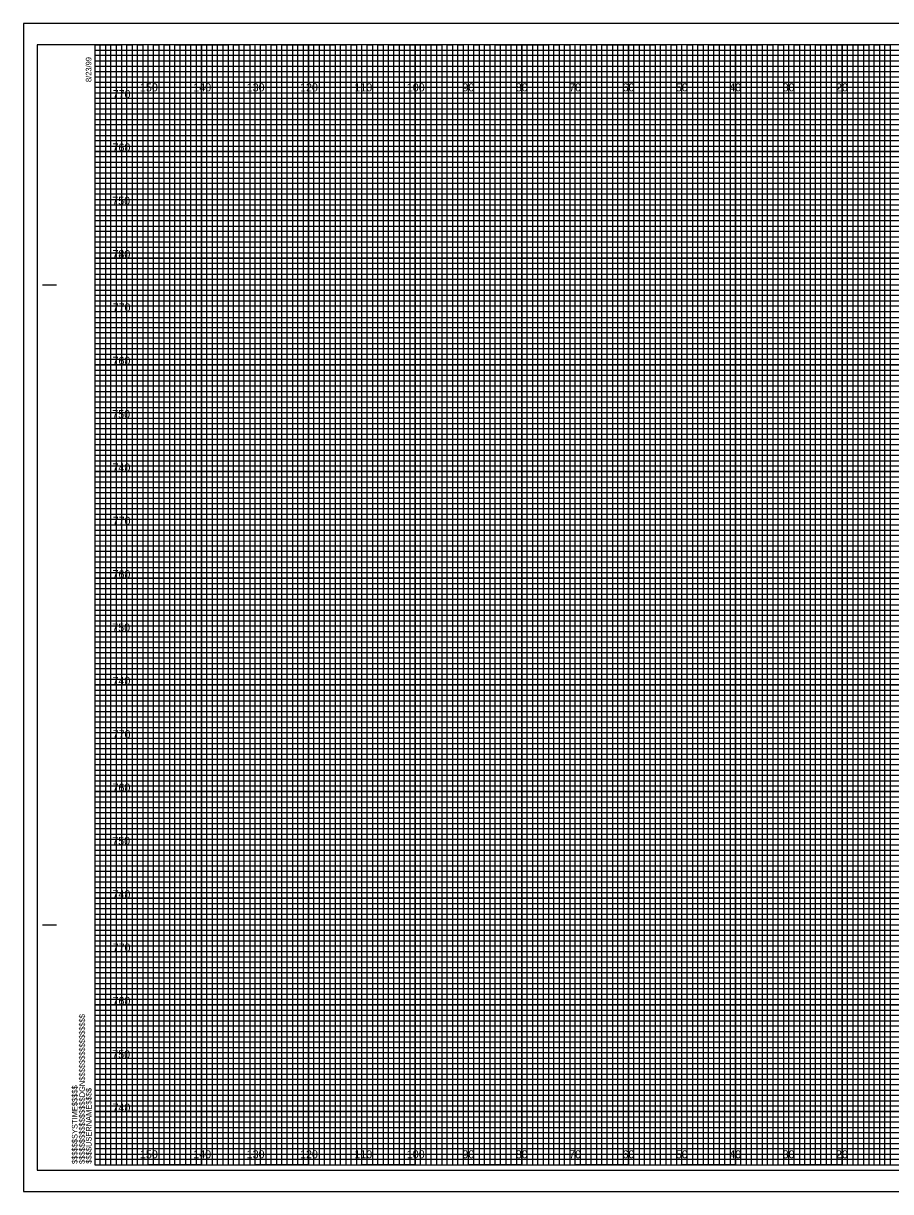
# Model space of a CAD drawing. Extents: x -13 to 323, y 435 to 654.
# Drawn here: x -13.4 to 149.1, y 435 to 654 of the extents above; entities that cross this region are included whole.
import ezdxf

# ---------------------------------------------------------------- set-up
doc = ezdxf.new("R2010")
doc.units = 0
for name, color, linetype in [('Exist Cross Section Cell', 7, 'Continuous'), ('Exist XS Ground Line', 7, 'Continuous'), ('Prop XS Ditch Slope Text', 7, 'Continuous'), ('Prop XS Dump Level', 7, 'Continuous'), ('Prop XS Finish Grade', 7, 'Continuous'), ('Prop XS Finish Grade Earthwork', 7, 'Continuous'), ('Prop XS Pvmt Edge Slope', 7, 'Continuous'), ('Prop XS SE Text', 7, 'Continuous'), ('Prop XS Side Slope Text', 7, 'Continuous'), ('Prop XS SS Elevation Text', 7, 'Continuous'), ('Prop XS Subgrade Earthwork', 7, 'Continuous')]:
    doc.layers.add(name, color=color, linetype=linetype)

msp = doc.modelspace()

# ---------------------------------------------------------------- linework, layer by layer
at = {"layer": 'Exist XS Ground Line'}
for p, q in [((10, 650), (0, 650)), ((10, 440), (10, 650)), ((30, 650), (20, 650)), ((20, 650), (20, 440)), ((30, 440), (30, 650)), ((50, 650), (40, 650)), ((40, 650), (40, 440)), ((50, 440), (50, 650)), ((70, 650), (60, 650)), ((60, 650), (60, 440)), ((70, 440), (70, 650)), ((90, 650), (80, 650)), ((80, 650), (80, 440)), ((90, 440), (90, 650)), ((110, 650), (100, 650)), ((100, 650), (100, 440)), ((110, 440), (110, 650)), ((130, 650), (120, 650)), ((120, 650), (120, 440)), ((130, 440), (130, 650)), ((150, 650), (140, 650)), ((140, 650), (140, 440)), ((20, 440), (10, 440)), ((40, 440), (30, 440)), ((60, 440), (50, 440)), ((80, 440), (70, 440)), ((100, 440), (90, 440)), ((120, 440), (110, 440)), ((140, 440), (130, 440))]:
    msp.add_line(p, q, dxfattribs=at)
for points in [[(0, 640), (320, 640), (320, 630), (0, 630)], [(0, 620), (320, 620), (320, 610), (0, 610)], [(0, 600), (320, 600), (320, 590), (0, 590)], [(0, 580), (320, 580), (320, 570), (0, 570)], [(0, 560), (320, 560), (320, 550), (0, 550)], [(0, 540), (320, 540), (320, 530), (0, 530)], [(0, 520), (320, 520), (320, 510), (0, 510)], [(0, 500), (320, 500), (320, 490), (0, 490)], [(0, 480), (320, 480), (320, 470), (0, 470)], [(0, 460), (320, 460), (320, 450), (0, 450)]]:
    msp.add_lwpolyline(points, dxfattribs=at)
at = {"layer": 'Prop XS Ditch Slope Text'}
msp.add_lwpolyline([(-13.4, 435), (323.3, 435), (323.3, 654), (-13.4, 654)], close=True, dxfattribs=at)
at = {"layer": 'Prop XS Dump Level'}
for p, q in [((0, 649), (260, 649)), ((260, 647.98), (0, 647.98)), ((0, 647.98), (0, 647)), ((0, 647), (260, 647)), ((260, 645.89), (0, 645.89)), ((0, 645.89), (0, 644)), ((0, 644), (320, 644))]:
    msp.add_line(p, q, dxfattribs=at)
for points in [[(0, 643), (270, 643), (320, 643), (320, 642), (0, 642)], [(0, 641), (320, 641), (320, 639), (0, 639)], [(0, 638), (320, 638), (320, 637), (0, 636.98)], [(0, 636), (320, 636), (320, 634), (0, 634)], [(0, 633), (320, 633), (320, 632), (0, 632)], [(0, 631), (320, 631), (320, 629), (0, 629)], [(0, 628), (320, 628), (320, 627), (0, 627)], [(0, 626), (320, 626), (320, 624), (0, 624)], [(0, 623), (320, 623), (320, 622), (0, 622)], [(0, 621), (320, 621), (320, 619), (0, 619)], [(0, 618), (320, 618), (320, 617), (0, 617)], [(0, 616), (320, 616), (320, 613.95), (320, 613), (320, 612), (0, 612)], [(0, 614), (320, 614), (320, 613), (0, 613)], [(0, 611), (320, 611), (320, 609), (0, 609.03)], [(0, 609.03), (320, 609), (320, 608), (0, 608)], [(0, 607), (320, 607), (320, 606), (0, 606)], [(0, 604), (320, 604), (320, 603), (0, 603)], [(0, 602), (320, 602), (320, 601), (0, 601)], [(-0.07, 598.89), (320, 598.89), (320, 597.88), (-0.07, 597.88)], [(0, 597), (320, 597), (320, 596), (0, 596)], [(0, 594), (320, 594), (320, 593), (0, 593)], [(0, 592), (320, 592), (320, 591), (0, 591)], [(0, 589), (320, 589), (320, 588), (0, 588)], [(0, 587), (320, 587), (320, 586), (0, 586)], [(0, 584), (320, 584), (320, 583), (0, 583)], [(0, 582), (320, 582), (320, 581), (0, 581)], [(0, 579), (320, 579), (319.99, 577.98), (0, 578)], [(0, 577), (320, 577), (320, 576), (0, 576)], [(0, 574), (320, 574), (320, 573), (0, 573)], [(0, 572), (320, 572), (320, 571), (0, 571)], [(0, 569), (320, 569), (320, 568), (0, 568)], [(0, 567), (320, 567), (320, 566), (0, 566)], [(0, 564), (320, 564), (320, 563), (0, 563)], [(0, 562), (320, 562), (320, 561), (0, 561)], [(0, 559), (320, 559), (320, 558), (0, 558)], [(0, 556.99), (320.07, 556.91), (320, 556), (0, 556)], [(0, 554), (320, 554), (320, 553), (0, 553)], [(0, 552), (320, 552), (320, 551), (0, 551)], [(0, 549), (320, 549), (320, 548), (0, 548)], [(0, 547), (320, 547), (320, 546), (0, 546)], [(0, 544), (320, 544), (320, 543), (0, 543)], [(0, 542), (320, 542), (320, 541), (0, 541)], [(0, 539), (320, 539), (320, 538), (0, 538)], [(0, 537), (320, 537), (320, 536), (0, 536)], [(0, 534), (320, 534), (320, 533), (0, 533)], [(0, 532), (320, 532), (320, 531), (0, 531)], [(0, 529), (320, 529), (320, 528), (0, 528)], [(0, 527), (320, 527), (320, 526), (0, 526)], [(0, 524), (320, 524), (320, 523), (0, 523)], [(0, 522), (320, 522), (320, 521), (0, 521)], [(0, 519), (320, 519), (319.99, 517.98), (0, 518)], [(0, 517), (320, 517), (320, 516), (0, 516)], [(0, 514), (320, 514), (320, 513), (0, 513)], [(0, 512), (320, 512), (320, 511), (0, 511)], [(0, 509), (320, 509), (320, 508), (0, 508)], [(0, 507), (320, 507), (320, 506), (0, 506)], [(0, 504), (320, 504), (320, 503), (0, 503)], [(0, 502), (320, 502), (320, 501), (0, 501)], [(0, 499), (320, 499), (320, 498), (0, 498)], [(0, 496.99), (320.07, 496.91), (320, 496), (0, 496)], [(0, 494), (320, 494), (320, 493), (0, 493)], [(0, 492), (320, 492), (320, 491), (0, 491)], [(0, 489), (320, 489), (320, 488), (0, 488)], [(0, 487), (320, 487), (320, 486), (0, 486)], [(0, 484), (320, 484), (320, 483), (0, 483)], [(0, 482), (320, 482), (320, 481), (0, 481)], [(0, 479), (320, 479), (320, 478), (0, 478)], [(0, 477), (320, 477), (320, 476), (0, 476)], [(0, 474), (320, 474), (320, 473), (0, 473)], [(0, 472), (320, 472), (320, 471), (0, 471)], [(0, 469), (320, 469), (320, 468), (0, 468)], [(0, 467), (320, 467), (320, 466), (0, 466)], [(0, 464), (320, 464), (320, 463), (0, 463)], [(0, 462), (320, 462), (320, 461), (0, 461)], [(0, 459), (320, 459), (320, 458), (0, 458)], [(0, 457), (320, 457), (320, 456), (0, 456)], [(0, 454), (320, 454), (320, 453), (0, 453)], [(0, 452), (320, 452), (320, 451), (0, 451)], [(0, 449), (320, 449), (320, 448), (0, 448)], [(0, 447), (320, 447), (320, 446), (0, 446)], [(0, 444), (320, 444), (320, 443), (0, 443)], [(0, 442), (320, 442), (320, 441), (0, 441)]]:
    msp.add_lwpolyline(points, dxfattribs=at)
at = {"layer": 'Prop XS Finish Grade'}
for p, q in [((323.3, 654), (-13.4, 654)), ((-13.4, 654), (-13.4, 435)), ((-13.4, 435), (323.3, 435))]:
    msp.add_line(p, q, dxfattribs=at)
at = {"layer": 'Prop XS Finish Grade Earthwork'}
msp.add_lwpolyline([(-10.8, 439), (322.4, 439), (322.4, 650), (-10.8, 650)], close=True, dxfattribs=at)
at = {"layer": 'Prop XS SE Text'}
for points in [[(0, 650), (5, 650), (5, 440), (15, 440), (15, 650), (25, 650), (25, 440), (35, 440), (35, 650), (45, 650), (45, 440), (55, 440), (55, 650), (65, 650), (65, 440), (75, 440), (75, 650), (85, 650), (85, 440), (95, 440), (95, 650), (105, 650), (105, 440), (115, 440), (115, 650), (125, 650), (125, 440), (135, 440), (135, 650), (145, 650), (145, 440), (155, 440)], [(0, 645), (275, 645)], [(0, 625), (320, 625), (320, 635), (0, 635)], [(0, 605), (320, 605), (320, 615), (0, 615)], [(0, 585), (320, 585), (320, 595), (0, 595)], [(0, 565), (320, 565), (320, 575), (0, 575)], [(0, 545), (320, 545), (320, 555), (0, 555)], [(0, 525), (320, 525), (320, 535), (0, 535)], [(0, 505), (320, 505), (320, 515), (0, 515)], [(0, 485), (320, 485), (320, 495), (0, 495)], [(0, 465), (320, 465), (320, 475), (0, 475)], [(0, 445), (320, 445), (320, 455), (0, 455)]]:
    msp.add_lwpolyline(points, dxfattribs=at)
at = {"layer": 'Prop XS Side Slope Text'}
for p, q in [((-9.8, 605), (-7.3, 605)), ((-9.7, 605), (-7.2, 605)), ((-9.8, 485), (-7.3, 485)), ((-9.7, 485), (-7.2, 485)), ((0, 440), (0, 440)), ((0, 440), (0, 440)), ((0, 440), (0, 440)), ((0, 440), (0, 440)), ((0, 440), (0, 440)), ((0, 440), (0, 440)), ((0, 440), (0, 440))]:
    msp.add_line(p, q, dxfattribs=at)
msp.add_lwpolyline([(320, 650), (0, 650), (0, 440), (320, 440)], close=True, dxfattribs=at)
at = {"layer": 'Prop XS SS Elevation Text'}
for points in [[(0, 440), (1, 440), (1, 650), (2, 650), (2, 440)], [(2, 440), (3, 440), (3, 650), (4, 650), (4, 440)], [(5, 440), (6, 440), (6, 650), (7, 650), (7, 440)], [(7, 440), (8, 440), (8, 650), (9, 650), (9, 440)], [(10, 440), (11, 440), (11, 650), (12, 650), (12, 440)], [(12, 440), (13, 440), (13, 650), (14, 650), (14, 440)], [(15, 440), (16, 440), (16, 650), (17, 650), (17, 440)], [(17, 440), (18, 440), (18, 650), (19, 650), (19, 440)], [(20, 440), (21, 440), (21, 650), (22, 650), (22, 440)], [(22, 440), (23, 440), (23, 650), (24, 650), (24, 440)], [(25, 440), (26, 440), (26, 650), (27, 650), (27, 440)], [(27, 440), (28, 440), (28, 650), (29, 650), (29, 440)], [(30, 440), (31, 440), (31, 650), (32, 650), (32, 440)], [(32, 440), (33, 440), (33, 650), (34, 650), (34, 440)], [(35, 440), (36, 440), (36, 650), (37, 650), (37, 440)], [(37, 440), (38, 440), (38, 650), (39, 650), (39, 440)], [(40, 440), (41, 440), (41, 650), (42, 650), (42, 440)], [(42, 440), (43, 440), (43, 650), (44, 650), (44, 440)], [(45, 440), (46, 440), (46, 650), (47, 650), (47, 440)], [(47, 440), (48, 440), (48, 650), (49, 650), (49, 440)], [(50, 440), (51, 440), (51, 650), (52, 650), (52, 440)], [(52, 440), (53, 440), (53, 650), (54, 650), (54, 440)], [(55, 440), (56, 440), (56, 650), (57, 650), (57, 440)], [(57, 440), (58, 440), (58, 650), (59, 650), (59, 440)], [(60, 440), (61, 440), (61, 650), (62, 650), (62, 440)], [(62, 440), (63, 440), (63, 650), (64, 650), (64, 440)], [(65, 440), (66, 440), (66, 650), (67, 650), (67, 440)], [(67, 440), (68, 440), (68, 650), (69, 650), (69, 440)], [(70, 440), (71, 440), (71, 650), (72, 650), (72, 440)], [(72, 440), (73, 440), (73, 650), (74, 650), (74, 440)], [(75, 440), (76, 440), (76, 650), (77, 650), (77, 440)], [(77, 440), (78, 440), (78, 650), (79, 650), (79, 440)], [(80, 440), (81, 440), (81, 650), (82, 650), (82, 440)], [(82, 440), (83, 440), (83, 650), (84, 650), (84, 440)], [(85, 440), (86, 440), (86, 650), (87, 650), (87, 440)], [(87, 440), (88, 440), (88, 650), (89, 650), (89, 440)], [(90, 440), (91, 440), (91, 650), (92, 650), (92, 440)], [(92, 440), (93, 440), (93, 650), (94, 650), (94, 440)], [(95, 440), (96, 440), (96, 650), (97, 650), (97, 440)], [(97, 440), (98, 440), (98, 650), (99, 650), (99, 440)], [(100, 440), (101, 440), (101, 650), (102, 650), (102, 440)], [(102, 440), (103, 440), (103, 650), (104, 650), (104, 440)], [(105, 440), (106, 440), (106, 650), (107, 650), (107, 440)], [(107, 440), (108, 440), (108, 650), (109, 650), (109, 440)], [(110, 440), (111, 440), (111, 650), (112, 650), (112, 440)], [(112, 440), (113, 440), (113, 650), (114, 650), (114, 440)], [(115, 440), (116, 440), (116, 650), (117, 650), (117, 440)], [(117, 440), (118, 440), (118, 650), (119, 650), (119, 440)], [(120, 440), (121, 440), (121, 650), (122, 650), (122, 440)], [(122, 440), (123, 440), (123, 650), (124, 650), (124, 440)], [(125, 440), (126, 440), (126, 650), (127, 650), (127, 440)], [(127, 440), (128, 440), (128, 650), (129, 650), (129, 440)], [(130, 440), (131, 440), (131, 650), (132, 650), (132, 440)], [(132, 440), (133, 440), (133, 650), (134, 650), (134, 440)], [(135, 440), (136, 440), (136, 650), (137, 650), (137, 440)], [(137, 440), (138, 440), (138, 650), (139, 650), (139, 440)], [(140, 440), (141, 440), (141, 650), (142, 650), (142, 440)], [(142, 440), (143, 440), (143, 650), (144, 650), (144, 440)], [(145, 440), (146, 440), (146, 650), (147, 650), (147, 440)], [(147, 440), (148, 440), (148, 650), (149, 650), (149, 440)]]:
    msp.add_lwpolyline(points, dxfattribs=at)
at = {"layer": 'Prop XS Subgrade Earthwork'}
for p, q in [((10, 440), (10, 650)), ((20, 440), (20, 650)), ((30, 440), (30, 650)), ((40, 440), (40, 650)), ((50, 440), (50, 650)), ((60, 440), (60, 650)), ((70, 440), (70, 650)), ((80, 440), (80, 650)), ((90, 440), (90, 650)), ((100, 440), (100, 650)), ((110, 440), (110, 650)), ((120, 440), (120, 650)), ((130, 440), (130, 650)), ((140, 440), (140, 650)), ((0, 640), (320, 640)), ((0, 630), (320, 630)), ((0, 620), (320, 620)), ((0, 610), (320, 610)), ((0, 600), (320, 600)), ((0, 590), (320, 590)), ((0, 580), (320, 580)), ((0, 570), (320, 570)), ((0, 560), (320, 560)), ((0, 550), (320, 550)), ((0, 540), (320, 540)), ((0, 530), (320, 530)), ((0, 520), (320, 520)), ((0, 510), (320, 510)), ((0, 500), (320, 500)), ((0, 490), (320, 490)), ((0, 480), (320, 480)), ((0, 470), (320, 470)), ((0, 460), (320, 460)), ((0, 450), (320, 450))]:
    msp.add_line(p, q, dxfattribs=at)

# ---------------------------------------------------------------- texts
at = {"layer": 'Exist Cross Section Cell'}
for s, p in [('150', (8.44, 641.25)), ('140', (18.44, 641.25)), ('130', (28.44, 641.25)), ('120', (38.44, 641.25)), ('110', (48.62, 641.25)), ('100', (58.44, 641.25)), ('90', (68.86, 641.25)), ('80', (78.86, 641.25)), ('70', (88.86, 641.25)), ('60', (98.86, 641.25)), ('50', (108.86, 641.25)), ('40', (118.86, 641.25)), ('30', (128.86, 641.25)), ('20', (138.86, 641.25)), ('150', (8.44, 441.25)), ('140', (18.44, 441.25)), ('130', (28.44, 441.25)), ('120', (38.44, 441.25)), ('110', (48.62, 441.25)), ('100', (58.44, 441.25)), ('90', (68.86, 441.25)), ('80', (78.86, 441.25)), ('70', (88.86, 441.25)), ('60', (98.86, 441.25)), ('50', (108.86, 441.25)), ('40', (118.86, 441.25)), ('30', (128.86, 441.25)), ('20', (138.86, 441.25))]:
    msp.add_text(s, height=1.5, dxfattribs=at).set_placement(p)
at = {"layer": 'Prop XS Pvmt Edge Slope'}
for s, p in [('770', (3.33, 640)), ('760', (3.3, 630)), ('750', (3.25, 620)), ('780', (3.28, 610)), ('740', (3.3, 610)), ('770', (3.33, 600)), ('760', (3.3, 590)), ('750', (3.25, 580)), ('740', (3.3, 570)), ('770', (3.33, 560)), ('760', (3.3, 550)), ('750', (3.25, 540)), ('740', (3.3, 530)), ('770', (3.33, 520)), ('760', (3.3, 510)), ('750', (3.25, 500)), ('740', (3.3, 490)), ('770', (3.33, 480)), ('760', (3.3, 470)), ('750', (3.25, 460)), ('740', (3.3, 450))]:
    msp.add_text(s, height=1.5, dxfattribs=at).set_placement(p)
at = {"layer": 'Prop XS Side Slope Text'}
for s, p in [('8/23/99', (-0.65, 643)), ('$$$$$$$$$$$$$$$$DGN$$$$$$$$$$$$$$$$', (-1.88, 440.18)), ('$$$$$$SYSTIME$$$$$', (-3.26, 440.18)), ('$$$$USERNAME$$$$', (-0.62, 440.23))]:
    msp.add_text(s, height=1.05, rotation=90, dxfattribs=at).set_placement(p)

doc.saveas('drawing.dxf')
